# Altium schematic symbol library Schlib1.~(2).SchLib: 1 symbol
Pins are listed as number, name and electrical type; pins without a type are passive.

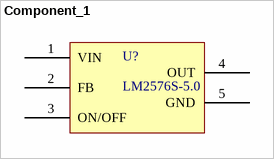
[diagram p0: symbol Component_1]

## Component_1
designator U?, comment LM2576S-5.0
footprint TO263-5A (263，5脚晶体管)
pins: 1 VIN, 2 FB, 3 ON/OFF, 4 OUT, 5 GND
